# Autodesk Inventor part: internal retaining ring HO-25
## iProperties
Shininess: 70.0
PropertySet Name: _Private Model Information
Created: 2001-01
Part Number: internal retaining ring HO-25
Document SubType Name: Modeling
Designer: rmjbm2
Control State: 0
Master: False
Checked Out: False
PropertySet Name: Design Tracking Control
Density: 0.0
Volumn: 0.0
Area: 0.0
PropertySet Name: Model Information
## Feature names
1. Extrusion2
